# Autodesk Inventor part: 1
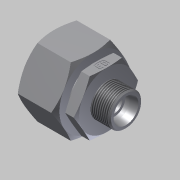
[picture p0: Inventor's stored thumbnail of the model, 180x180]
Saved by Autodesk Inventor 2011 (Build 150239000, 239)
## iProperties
Created: 2016-09
Part Number: 1
Document SubType Name: Modeling
Designer: Храмов
Density: 1 g/cm^3
Author: Храмов
Стандарт преобразования: STEP AP203
Имя файла: C:/Users/dorohin/Documents/EO Tube end reducer RED30_16SOMDCF.stp
Постпроцессор: Build: 239, Release: 2011 RTM - Date: Wed 02/17/2010
Отправленные единицы: миллиметр
Неопределенность: 1.0000000000000002e-06
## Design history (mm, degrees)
feature "БазТело1"
feature "Резьба1" dims "d0" = 10, "d1" = 0
feature "Резьба2" dims "d2" = 10, "d3" = 0
node "1"
